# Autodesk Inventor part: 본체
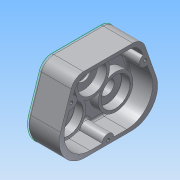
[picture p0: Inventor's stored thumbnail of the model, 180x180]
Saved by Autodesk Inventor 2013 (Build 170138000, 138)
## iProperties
Created: 2014-12
Part Number: 본체
Material: 알루미늄 6061
Document SubType Name: 판금
Designer: Administrator
Density: 2.71 g/cm^3
Sheet Metal Rule: 기본값
Mass: 625.749 g
Surface Area: 680.786 cm^2
Volume: 230.904 cm^3
Author: Administrator
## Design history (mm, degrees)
sketch "스케치7"
  geometry: L1 (-47, 95.766)-(47, 95.766); L2 (-81.323, -8.357)-(83.342, -8.357); L3 (-47, 95.766)-(-81.323, -8.357); L4 (47, 95.766)-(83.342, -8.357); L5 (-41.714, 59.766)-(46.616, 59.766); L6 (-71.75, 27.643)-(66.305, 27.643); L7 (0, 59.766)-(79.665, -19.899); L8 (0, 59.766)-(-78.474, -18.708); L9 (-51.288, 27.643)-(46, 27.643); C1 r 24 at (-32.527, 27.24); C2 r 24 at (32.527, 27.24); A1 r 46 centre (0, 59.766) between (-32.527, 27.24) and (32.527, 27.24); 1 further point
  constraints: 18 end point, 4 point on line, 3 centre point, 3 parallel, 2 point on circle, 1 collinear, 1 horizontal
  dimensions: "d39" = 94 distance of L1.start L1.end; "d41" = 36 distance between parallel lines of L5 L1; "d42" = 36 vertical distance of L2.end L6.end; "d43" = 47 horizontal distance of L1.end point (0, 0); "d109" = 92 diameter of A1; "d110" = 45 deg angle of L7 L5; "d111" = 90 deg angle of L8 L7; "d112" = 48 diameter of C1; "d113" = 48 diameter of C2
extrude "돌출3" new body sketch "스케치7" distance "d44" = 44; taper "d45" = 0 deg
sketch "스케치8"
  geometry: L1 (-95.766, 47)-(-95.766, -47) reference; L2 (8.357, -81.323)-(8.357, 83.342) reference; L3 (-90.766, 42)-(-90.766, -42); L4 (3.357, 78.342)-(3.357, -76.323); L5 (-90.766, 42)-(3.357, 78.342); L6 (-90.766, -42)-(3.357, -76.323); 1 further point
  constraints: 8 end point, 2 parallel
  dimensions: "d46" = 5 distance between parallel lines of L3 L1; "d47" = 5 distance between parallel lines of L2 L4; "d48" = 5 horizontal distance of L3.start L1.start; "d49" = 5 horizontal distance of L3.end L1.end; "d50" = 5 horizontal distance of L4.start L2.end; "d51" = 5 horizontal distance of L2.start L4.end
extrude "돌출4" cut sketch "스케치8" distance "d52" = 34; taper "d53" = 0 deg
sketch "스케치9"
  geometry: L1 (3.357, 78.342)-(3.357, -76.323) reference; L2 (-59.766, -37.087)-(-59.766, 37.087); L3 (-95.766, 47)-(-95.766, -47) reference; L4 (-27.643, -62.206)-(-27.643, 91.792); L5 (8.357, -81.323)-(8.357, 83.342) reference; L6 (-59.766, 0)-(3.357, 0); C1 r 20 at (-59.766, 0); C2 r 10 at (-59.766, 0); C3 r 24 at (-59.766, 0); 2 further points
  constraints: 6 end point, 3 centre point, 3 coincident, 2 parallel, 1 midpoint, 1 perpendicular, 1 point on line
  dimensions: "d56" = 36 distance from line of L3 L2.end; "d66" = 36 distance between parallel lines of L5 L4
extrude "돌출5" join sketch "스케치9" distance "d67" = 12; taper "d68" = 0 deg
extrude "돌출6" cut sketch "스케치9" distance "d69" = 3; taper "d70" = 0 deg
extrude "돌출7" join sketch "스케치9" distance "d71" = 12; taper "d72" = 0 deg
sketch "스케치10"
  geometry: L1 (-90.766, -42)-(-90.766, 42) reference; L2 (3.357, -76.323)-(-90.766, -42) reference; L3 (3.357, 78.342)-(3.357, -76.323) reference; L4 (-90.766, 42)-(3.357, 78.342) reference; L5 (-59.766, 0)-(18.438, 78.204); L6 (-59.766, 0)-(17.496, -77.263); L7 (-59.766, -37.087)-(-59.766, 37.087) reference; C1 r 24 at (-59.766, 0) reference; 1 further point
  constraints: 4 end point
  dimensions: "d73" = 90 deg angle of L5 L6; "d74" = 45 deg angle of L6 L7
fillet "모깎기3" dims "d75" = 18
fillet "모깎기4" dims "d76" = 18
fillet "모깎기5" dims "d77" = 36
sketch "스케치11"
  geometry: L1 (-79.25, 46.447)-(-45.61, 59.435) reference; L2 (-44.977, -58.698)-(-78.933, -46.315) reference; L3 (3.357, 25.852)-(3.357, -24.876) reference; L4 (-66.766, 51.267)-(-66.766, -50.752); L5 (-95.766, 34.218)-(-95.766, -33.981) reference; L6 (0, 0)-(77.153, 0); L7 (3.357, 25.852)-(3.357, -24.876) reference; A1 r 8 centre (-66.766, -50.752) between (-59.251, -53.493) and (-74.282, -48.011); A2 r 8 centre (-66.766, 51.267) between (-74.229, 48.385) and (-59.303, 54.148); A3 r 8 centre (3.357, 0) between (3.357, 8) and (3.357, -8); 3 further points
  constraints: 10 point on line, 6 point on circle, 5 coincident, 4 end point, 3 centre point, 1 parallel, 1 perpendicular
  dimensions: "d79" = 29 distance between parallel lines of L4 L5; "d80" = 16 diameter of A1; "d81" = 16 diameter of A2; "d82" = 16 diameter of A3
extrude "돌출8" join sketch "스케치11" distance "d83" = 34; taper "d84" = 0 deg
sketch "스케치14"
  geometry: L1 (95.766, -33.981)-(95.766, 34.218) reference; 2 further points
  constraints: 1 horizontal alignment, 1 other
  dimensions: "d88" = 30 distance from line of point (65.766, 0) L1
feature "엠보싱1" sketch "스케치14" dims "d39" = 94, "d41" = 36, "d42" = 36, "d43" = 47, "d92" = 1, "d93" = 0, "d109" = 92, "d110" = 45 deg, "d111" = 90 deg, "d112" = 48, "d113" = 48
sketch "스케치15"
  geometry: L1 (-8.357, 32.647)-(-8.357, -31.551) reference; L2 (38.914, -65.741)-(83.402, -51.076) reference; L3 (95.766, -33.981)-(95.766, 34.218) reference; L4 (83.698, 51.212)-(39.507, 66.636) reference; L5 (66.031, -18.016)-(64.46, -18.016) reference; L6 (64.704, -21.598)-(64.256, -21.655) reference; L7 (63.979, -17.479)-(68.335, -17.479) reference; L8 (68.335, -17.479)-(68.335, -20.955) reference; L9 (68.335, -20.955)-(67.887, -20.955) reference; L10 (67.887, -20.955)-(67.887, -18.016) reference; L11 (67.887, -18.016)-(66.479, -18.016) reference; L12 (66.479, -18.016)-(66.479, -20.638) reference; L13 (66.479, -20.638)-(66.031, -20.638) reference; L14 (66.031, -20.638)-(66.031, -18.016) reference; L15 (69.019, -14.939)-(63.768, -14.939) reference; L16 (63.768, -14.939)-(63.768, -14.393) reference; L17 (63.768, -14.393)-(69.271, -14.393) reference; L18 (69.271, -14.393)-(69.271, -14.825) reference; L19 (68.897, -13.547)-(64.069, -13.547) reference; L20 (64.069, -13.547)-(64.069, -13.001) reference; L21 (64.069, -13.001)-(66.975, -13.001) reference; L22 (66.975, -13.001)-(66.975, -11.764) reference; L23 (66.975, -11.764)-(67.391, -11.764) reference; L24 (67.391, -11.764)-(67.391, -13.001) reference; L25 (67.391, -13.001)-(69.182, -13.001) reference; L26 (69.182, -13.001)-(69.182, -13.449) reference; L27 (62.612, -15.11)-(62.164, -15.11) reference; L28 (62.164, -15.11)-(62.164, -9.924) reference; L29 (62.164, -9.924)-(64.46, -9.924) reference; L30 (64.46, -9.924)-(64.46, -10.323) reference; L31 (64.216, -10.461)-(62.612, -10.461) reference; L32 (62.612, -10.461)-(62.612, -15.11) reference; L33 (65.469, -12.497)-(65.054, -12.13) reference; L34 (64.81, -8.898)-(65.217, -8.524) reference; L35 (68.954, -10.404)-(68.954, -10.885) reference; L36 (64.59, -7.237)-(64.59, -7.775) reference; L37 (66.878, -7.726)-(66.878, -7.18) reference; L38 (68.628, -1.832)-(68.131, -1.832) reference; L39 (68.131, -1.832)-(68.131, 0.041) reference; L40 (68.131, 0.041)-(62.628, 0.041) reference; L41 (62.628, 0.041)-(62.628, 0.586) reference; L42 (62.628, 0.586)-(68.131, 0.586) reference; L43 (68.131, 0.586)-(68.131, 2.45) reference; L44 (68.131, 2.45)-(68.628, 2.45) reference; L45 (68.628, 2.45)-(68.628, -1.832) reference; L46 (64.745, 12.114)-(64.745, 9.94) reference; L47 (64.745, 9.94)-(62.197, 9.94) reference; L48 (62.197, 9.94)-(62.197, 10.494) reference; L49 (62.197, 10.494)-(64.297, 10.494) reference; L50 (64.297, 10.494)-(64.297, 15.094) reference; L51 (64.297, 15.094)-(64.745, 15.094) reference; L52 (64.745, 15.094)-(64.745, 12.659) reference; L53 (64.745, 12.659)-(66.21, 12.659) reference; L54 (66.21, 12.659)-(66.21, 15.973) reference; L55 (66.21, 15.973)-(66.658, 15.973) reference; L56 (66.658, 15.973)-(66.658, 10.73) reference; L57 (68.661, 10.388)-(68.661, 14.955) reference; L58 (68.661, 14.955)-(69.117, 14.955) reference; L59 (69.117, 14.955)-(69.117, 9.81) reference; L60 (66.658, 10.136)-(66.658, 8.768) reference; L61 (66.658, 8.768)-(66.21, 8.768) reference; L62 (66.21, 8.768)-(66.21, 12.114) reference; L63 (66.21, 12.114)-(64.745, 12.114) reference; L64 (62.628, 3.501)-(64.46, 4.168) reference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; A1 r 36 centre (27.643, 32.647) between (39.507, 66.636) and (-8.357, 32.647) reference; A2 r 36 centre (27.643, -31.551) between (-8.357, -31.551) and (38.914, -65.741) reference; A3 r 18 centre (77.766, -33.981) between (83.402, -51.076) and (95.766, -33.981) reference; A4 r 18 centre (77.766, 34.218) between (95.766, 34.218) and (83.698, 51.212) reference; 54 further points
  constraints: 68 other
sketch "스케치16"
  geometry: L1 (3.357, 25.852)-(3.357, 8) reference; L2 (-59.766, 0)-(-59.766, 39.774); L3 (-7.973, 51.794)-(-59.766, 0); L4 (-59.766, 0)-(4.694, -64.461); L5 (-27.24, -32.527)-(-27.24, 32.527); C1 r 24 at (-59.766, 0) reference; C2 r 24 at (-27.24, -32.527); C3 r 24 at (-27.24, 32.527); A1 r 46 centre (-59.766, 0) between (-27.24, -32.527) and (-27.24, 32.527); 1 further point
  constraints: 8 end point, 3 centre point, 2 point on circle, 2 point on line, 1 coincident, 1 parallel
  dimensions: "d98" = 46 radius of A1; "d103" = 45 deg angle of L3 L2; "d105" = 90 deg angle of L3 L4; "d107" = 48 diameter of C2; "d108" = 48 diameter of C3
extrude "돌출9" join sketch "스케치16" distance "d114" = 12; taper "d115" = 0 deg
sketch "스케치17"
  geometry: C1 r 20 at (-27.24, 32.527); C2 r 20 at (-27.24, -32.527); A1 r 24 centre (-27.24, -32.527) between (-48.351, -21.111) and (-38.655, -11.416) reference; A2 r 24 centre (-27.24, 32.527) between (-38.655, 11.416) and (-48.351, 21.111) reference; 1 further point
  constraints: 2 centre point, 2 coincident
  dimensions: "d116" = 40 diameter of C2; "d118" = 40 diameter of C1
extrude "돌출10" cut sketch "스케치17" distance "d119" = 12; taper "d120" = 0 deg
sketch "스케치20"
  geometry: C1 r 10 at (-59.766, 0) reference; C2 r 20 at (-59.766, 0); 1 further point
  constraints: 1 centre point, 1 coincident
  dimensions: "d125" = 40 diameter of C2
extrude "돌출11" cut sketch "스케치20" distance "d127" = 12; taper "d128" = 0 deg
sketch "스케치21"
  geometry: C1 r 20 at (0, 0) reference; C2 r 10 at (0, 0); 1 further point
  constraints: 1 centre point, 1 coincident
  dimensions: "d129" = 20 diameter of C2
sketch "스케치22"
  geometry: C1 r 20 at (0, 0) reference; C2 r 10 at (0, 0); 1 further point
  constraints: 1 centre point, 1 coincident
  dimensions: "d131" = 20 diameter of C2
extrude "돌출12" cut sketch "스케치21" stored distance "d133" = 12; taper "d134" = 0 deg
extrude "돌출13" cut sketch "스케치22" stored distance "d135" = 12; taper "d136" = 0 deg
sketch "스케치25"
  geometry: C1 r 10 at (27.24, -32.527) reference; C2 r 15 at (27.643, 32.647); C3 r 15 at (27.24, -32.527); C4 r 20 at (27.643, 32.647); C5 r 20 at (27.24, -32.527); A1 r 36 centre (27.643, 32.647) between (39.507, 66.636) and (-8.357, 32.647) reference; 1 further point
  constraints: 4 centre point, 4 coincident
  dimensions: "d144" = 40 diameter of C5; "d146" = 40 diameter of C4; "d147" = 30 diameter of C2; "d148" = 30 diameter of C3
extrude "돌출15" join sketch "스케치25" distance "d149" = 7; taper "d150" = 0 deg
sketch "스케치26"
  geometry: A1 r 8 centre (-66.766, -50.752) between (-59.251, -53.493) and (-74.282, -48.011) reference; A2 r 8 centre (-66.766, 51.267) between (-74.229, 48.385) and (-59.303, 54.148) reference; A3 r 8 centre (3.357, 0) between (3.357, 8) and (3.357, -8) reference; 4 further points
  constraints: 3 coincident
hole "구멍1" sketch "스케치26" at (-66.766, 51.267), (-66.766, -50.752), (3.357, 0) diameter "d151" = 4.134; stored, may be unused: countersink angle "d155" = 90 deg, drill point angle "d157" = 118 deg; dims "d152" = 20, "d153" = 4, "d154" = 2, "d156" = 23
fillet "모깎기6" dims "d158" = 3
fillet "모깎기7" dims "d159" = 0.3
chamfer "모따기1" distance "d160" = 0.1; stored, may be unused: second distance "d161" = 2, angle "d162" = 45 deg
node "솔리드2"
other parameters: "K계수" = 4.4, "BendRadius" = 0.5 (derived), "BendReliefWidth" = 0.5 (derived), "BendReliefDepth" = 0.25 (derived), "CornerReliefSize" = 2 (derived), "SeamGap" = 0.01, "MinimumRemnant" = 1 (derived), "TransitionRadius" = 0.5 (= BendRadius)
